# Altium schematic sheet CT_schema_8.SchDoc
size 251 x 159 mm
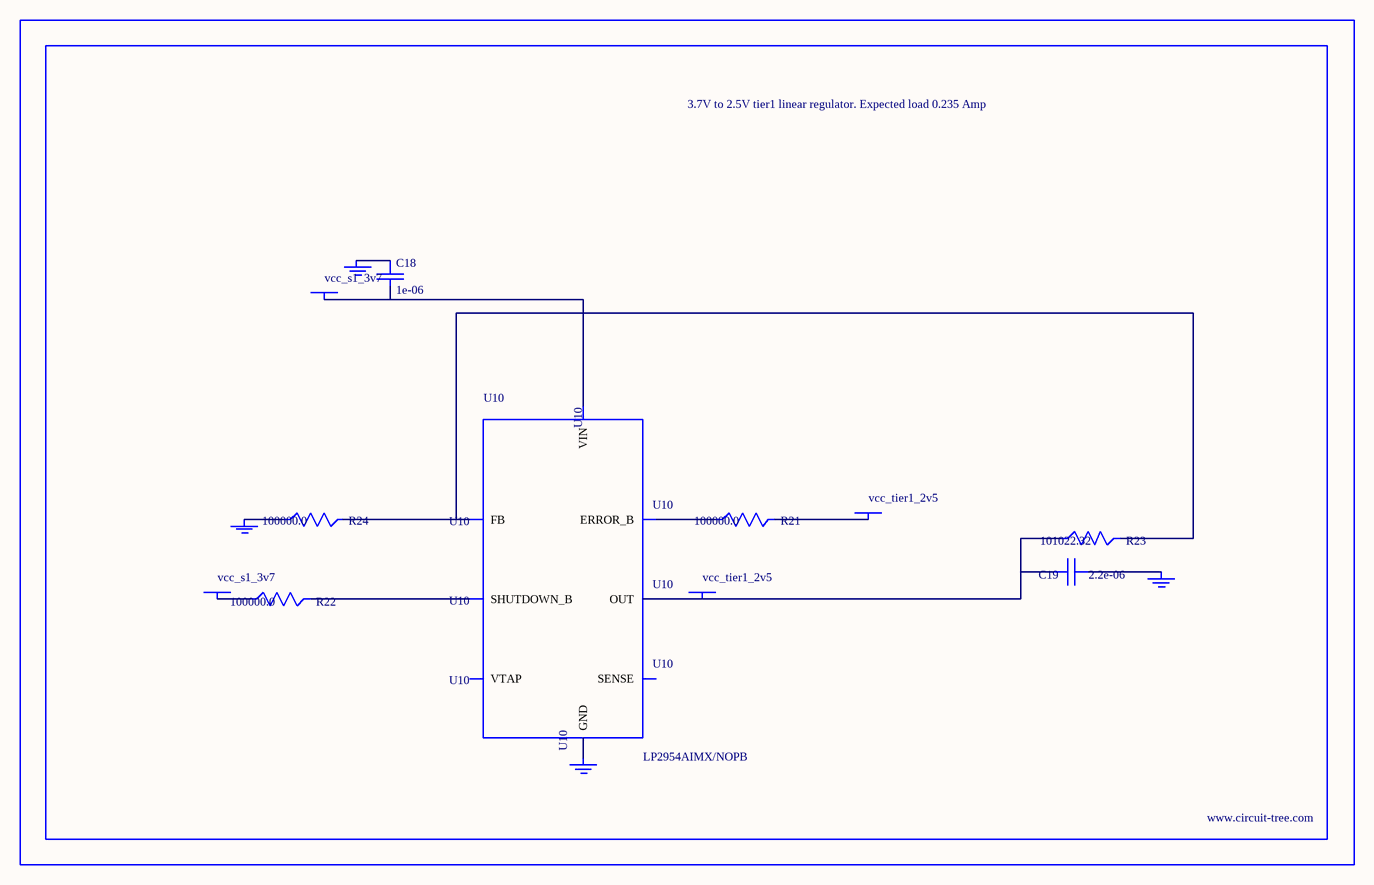
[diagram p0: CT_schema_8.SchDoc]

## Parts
BORDER7  (no value)
C18  1e-06  [EXV-9B]
C19  2.2e-06  [EXV-9B]
GND_INSTANCE_7_0  (no value)
GND_INSTANCE_7_1  (no value)
GND_INSTANCE_7_2  (no value)
GND_INSTANCE_7_3  (no value)
POWER_INSTANCE_7_0  vcc_s1_3v7
POWER_INSTANCE_7_1  vcc_tier1_2v5
POWER_INSTANCE_7_2  vcc_s1_3v7
POWER_INSTANCE_7_3  vcc_tier1_2v5
R21  100000.0  [R0603]
R22  100000.0  [R0603]
R23  101022.32  [R0603]
R24  100000.0  [R0603]
U10  LP2954AIMX/NOPB  [LP2954]

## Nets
NetC18_1: C18.1 GND_INSTANCE_7_2.0(GND)
NetC18_2: C18.2 POWER_INSTANCE_7_2.0(PWR) U10.8(VIN)
NetC19_1: C19.1 GND_INSTANCE_7_0.0(GND)
NetC19_2: C19.2 POWER_INSTANCE_7_3.0(PWR) R23.1 U10.1(OUT)
NetGND_INSTANCE_7_1_0: GND_INSTANCE_7_1.0(GND) R24.1
NetGND_INSTANCE_7_3_0: GND_INSTANCE_7_3.0(GND) U10.4(GND)
NetPOWER_INSTANCE_7_0_0: POWER_INSTANCE_7_0.0(PWR) R22.1
NetPOWER_INSTANCE_7_1_0: POWER_INSTANCE_7_1.0(PWR) R21.2
NetR21_1: R21.1 U10.5(ERROR_B)
NetR22_2: R22.2 U10.3(SHUTDOWN_B)
NetR23_2: R23.2 R24.2 U10.7(FB)

Not connected (* = marked no-connect by the designer): U10 2(SENSE) 6(VTAP)

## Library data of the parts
BORDER7 = BORDER_PAGE7
C18 = EDK105M050A9BAA
C19 = EDK225M050A9BAA
GND_INSTANCE_7_0-GND_INSTANCE_7_3 = GND
POWER_INSTANCE_7_0-POWER_INSTANCE_7_3 = PWR
R21 R22 R24 = RC0603JR-07100KL
R23 = R23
